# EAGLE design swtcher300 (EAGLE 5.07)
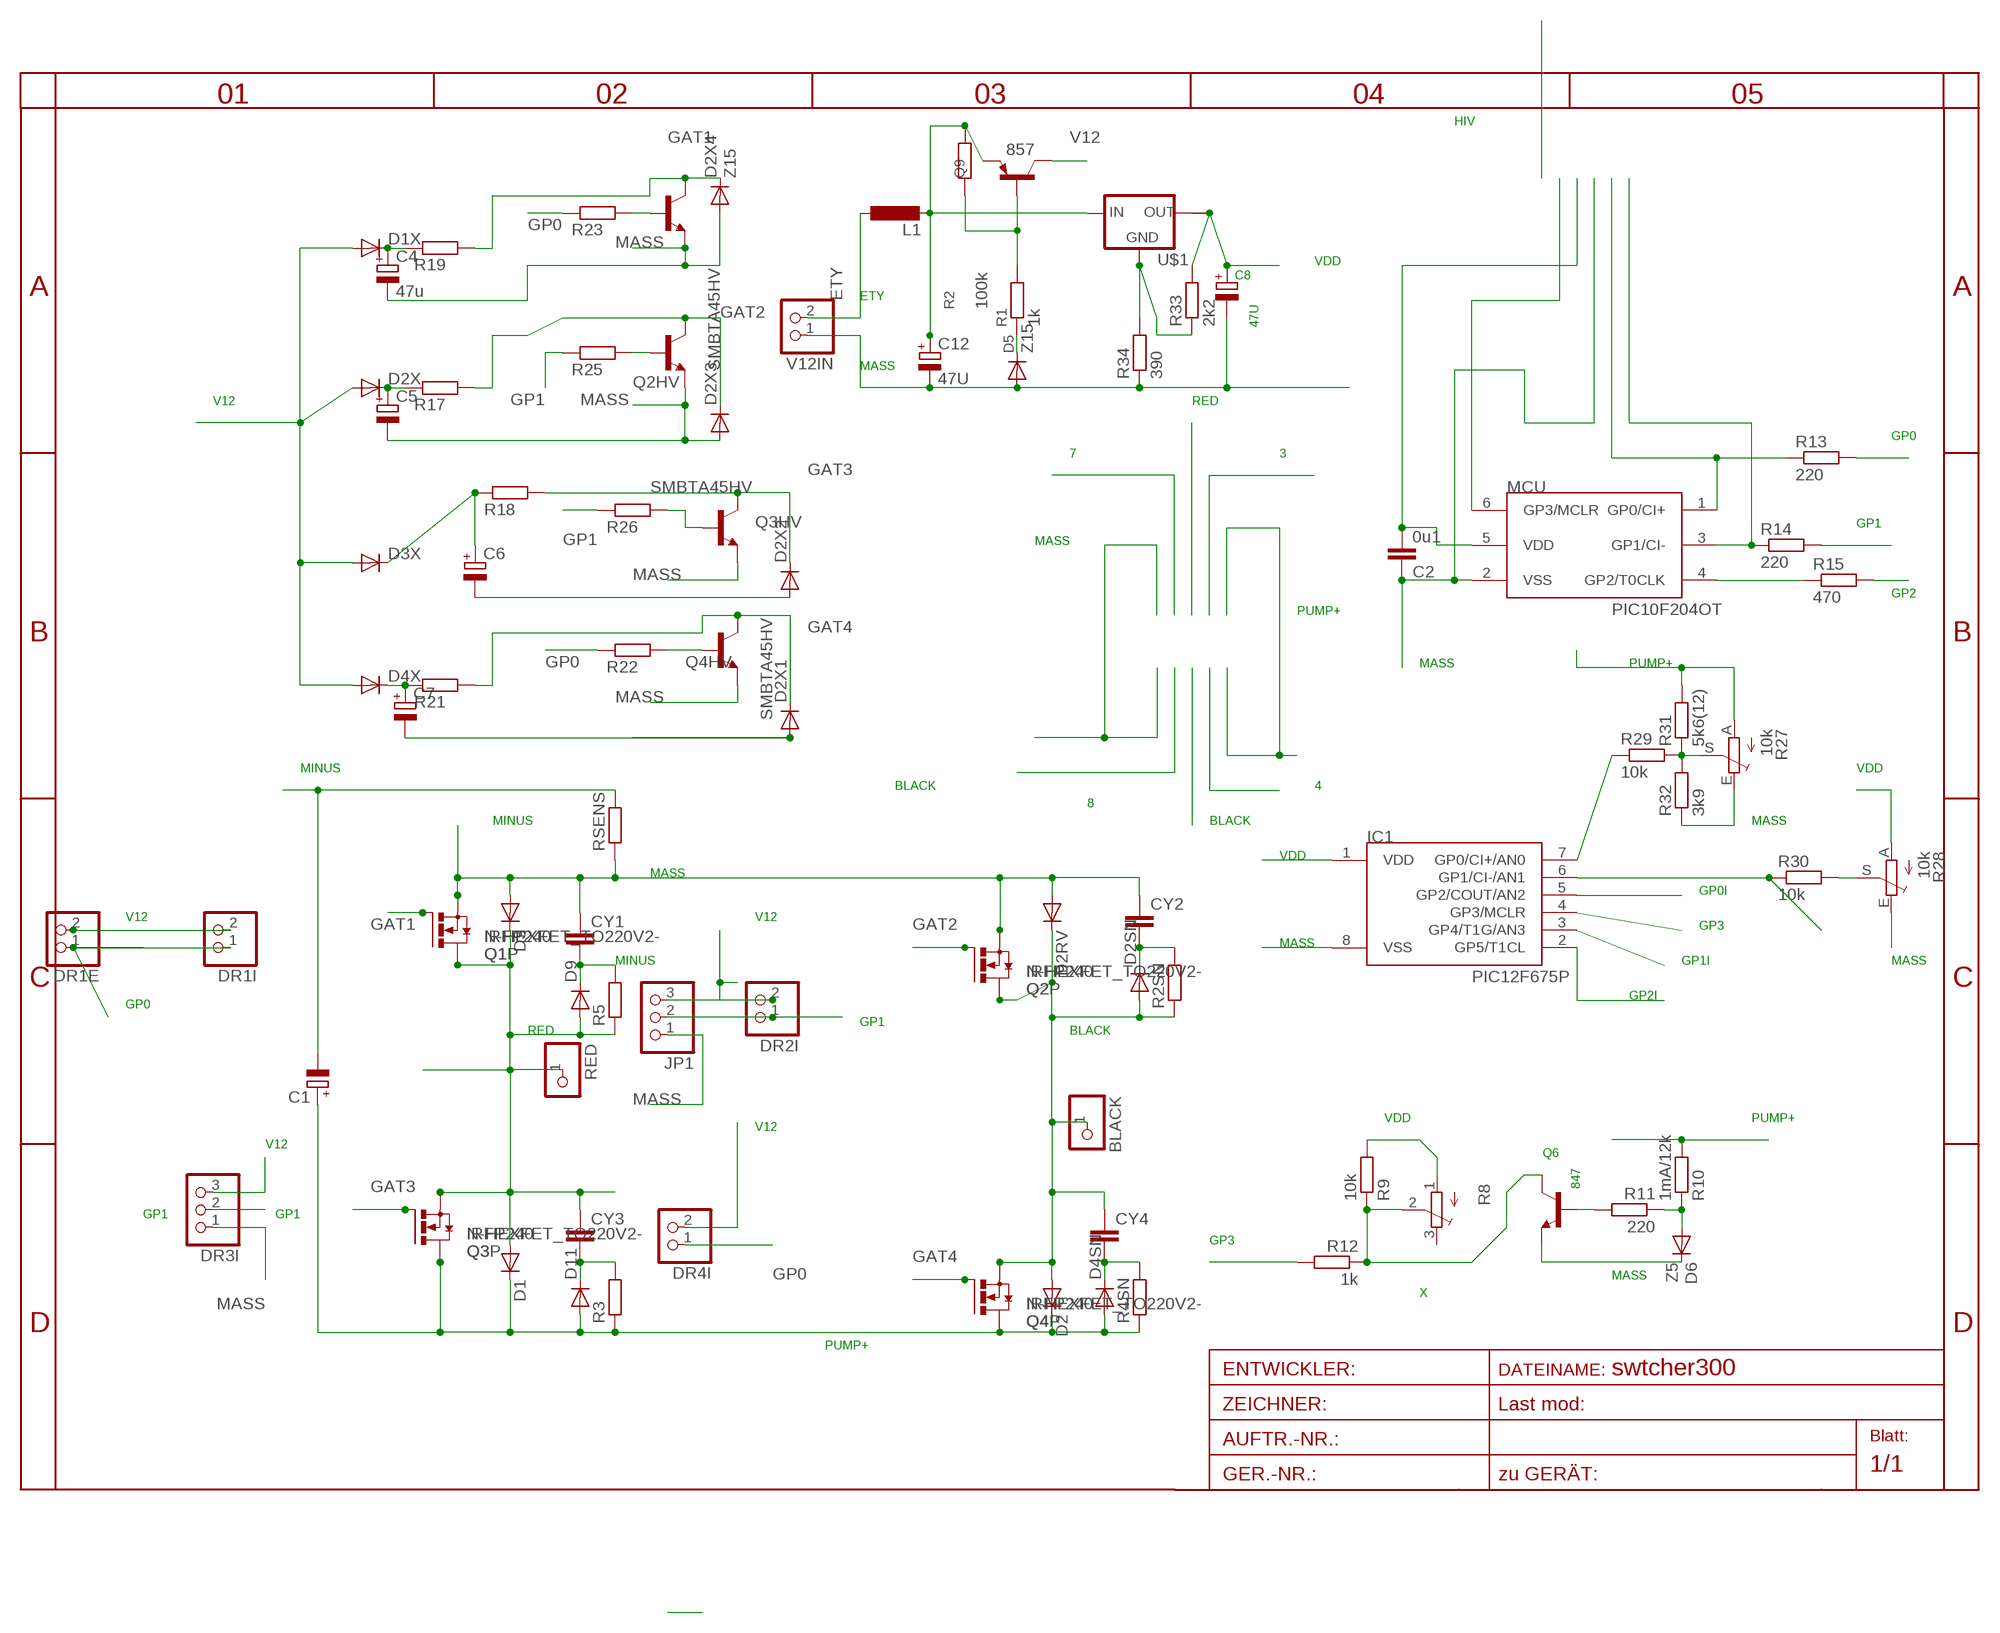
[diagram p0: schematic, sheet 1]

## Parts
BLACK  PINHD-1X14.5MM  [1X4MM5]
C1  CPOL-EUE5-13  [E5-13]
C2  0u1  C-EUC0805  [C0805]
C4  47u  CPOL-EUE  [PANASONIC_E]
C5  CPOL-EUE  [PANASONIC_E]
C6  CPOL-EUE  [PANASONIC_E]
C7  CPOL-EUE  [PANASONIC_E]
C8  47U  CPOL-EUE  [PANASONIC_E]
C12  47U  CPOL-EUE  [PANASONIC_E]
CY1  CXXC22B10  [XC22B10]
CY2  CXXC22B10  [XC22B10]
CY3  CXXC22B10  [XC22B10]
CY4  CXXC22B10  [XC22B10]
D1  DIODE-SMC  [SMC]
D1X  DIODE-SMA-DO214  [SMA-DO214AC]
D2  DIODE-SMC  [SMC]
D2RV  DIODE-SMC  [SMC]
D2SN  DIODE-SOD61E  [SOD61E]
D2X  DIODE-SMA-DO214  [SMA-DO214AC]
D2X1  DIODE-MINIMELF  [MINIMELF]
D2X2  DIODE-MINIMELF  [MINIMELF]
D2X3  DIODE-MINIMELF  [MINIMELF]
D2X4  Z15  DIODE-MINIMELF  [MINIMELF]
D3  DIODE-SMC  [SMC]
D3X  DIODE-SMA-DO214  [SMA-DO214AC]
D4SN  DIODE-SOD61E  [SOD61E]
D4X  DIODE-SMA-DO214  [SMA-DO214AC]
D5  Z15  DIODE-MINIMELF  [MINIMELF]
D6  Z5  DIODE-MINIMELF  [MINIMELF]
D9  DIODE-SOD61E  [SOD61E]
D11  DIODE-SOD61E  [SOD61E]
DR1E  PINHD-1X2STR  [1X02]
DR1I  PINHD-1X2STR  [1X02]
DR2I  PINHD-1X2STR  [1X02]
DR3I  PINHD-1X3  [1X03]
DR4I  PINHD-1X2STR  [1X02]
IC1  PIC12F675P  [DIL8]
JP1  PINHD-1X3  [1X03]
L1  L-EU0204/5  [0204/5]
MCU  PIC10F204OT  [SOT23-6]
Q1  IRFP240  [TO247BV]
Q1P  N-HEXFET_TO220V2-  [TO220BV2]
Q2  IRFP240  [TO247BV]
Q2HV  SMBTA45HV  [SOT23HV]
Q2P  N-HEXFET_TO220V2-  [TO220BV2]
Q3  IRFP240  [TO247BV]
Q3HV  SMBTA45HV  [SOT23HV]
Q3P  N-HEXFET_TO220V2-  [TO220BV2]
Q4  IRFP240  [TO247BV]
Q4HV  SMBTA45HV  [SOT23HV]
Q4P  N-HEXFET_TO220V2-  [TO220BV2]
Q6  847  BC847ALT1SMD  [SOT23]
Q9  857  BC857ALT1SMD  [SOT23-BEC]
QH1  SMBTA45HV  [SOT23HV]
R1  1k  R-EU_R0805  [R0805]
R2  100k  R-EU_R0805  [R0805]
R2SN  R-EU_0617/22  [0617/22]
R3  R-EU_0617/17  [0617/17]
R4SN  R-EU_0617/22  [0617/22]
R5  R-EU_0617/22  [0617/22]
R8  TRIM_EU-3223W  [3223W]
R9  10k  R-EU_R1206  [R1206]
R10  1mA/12k  R-EU_R1206  [R1206]
R11  220  R-EU_R1206  [R1206]
R12  1k  R-EU_0204/7  [0204/7]
R13  220  R-EU_R1206  [R1206]
R14  220  R-EU_0207/10  [0207/10]
R15  470  R-EU_0207/20  [0207/20]
R17  R-EU_R1206  [R1206]
R18  R-EU_R1206  [R1206]
R19  R-EU_R1206  [R1206]
R21  R-EU_R1206  [R1206]
R22  R-EU_R1206  [R1206]
R23  R-EU_R1206  [R1206]
R25  R-EU_R1206  [R1206]
R26  R-EU_R0805  [R0805]
R27  10k  TRIM_EU-RAND160  [RANDL]
R28  10k  TRIM_EU-RAND160  [RANDL]
R29  10k  R-EU_0207/30  [0207/30]
R30  10k  R-EU_R0805  [R0805]
R31  5k6(12)  R-EU_0207/30  [0207/30]
R32  3k9  R-EU_R0805  [R0805]
R33  2k2  R-EU_R0805  [R0805]
R34  390  R-EU_R0805  [R0805]
RED  PINHD-1X14.5MM  [1X4MM5]
RSENS  R-EU_CERAM35  [CERAM35]
U$1  AP1117  [SOT223]
V12IN  PINHD-1X2STR  [1X02]

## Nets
BLACK: BLACK.1 C7.- CY4.1 D2.A D2RV.C D2SN.A D2X1.A Q2.D Q2P.D Q4.S Q4P.S R2SN.1
ETY: L1.1 V12IN.2
GAT1: D2X4.C Q1.G Q1P.G QH1.3(C) R19.2
GAT2: D2X3.C Q2.G Q2HV.3(C) Q2P.G R17.2
GAT3: D2X2.C Q3.G Q3HV.3(C) Q3P.G R18.2
GAT4: D2X1.C Q4.G Q4HV.3(C) Q4P.G R21.2
GP0: DR1E.1 DR1I.1 DR4I.1 R13.2 R22.1 R23.1
GP0I: IC1.5(GP2/COUT/AN2) MCU.1(GP0/CI+) R13.1
GP1: DR2I.1 DR3I.2 JP1.2 R14.2 R25.1 R26.1
GP1I: IC1.3(GP4/T1G/AN3) MCU.3(GP1/CI-) R14.1
GP2: R15.2
GP2I: IC1.2(GP5/T1CL) MCU.4(GP2/T0CLK) R15.1
GP3: IC1.4(GP3/MCLR) MCU.6(GP3/MCLR) R12.2
MASS: C2.1 C4.- C5.- C8.- C12.- CY1.1 CY2.1 D2RV.A D2X3.A D2X4.A D3.A D5.A D6.C DR3I.1 IC1.8(VSS) JP1.1 MCU.2(VSS) Q1.S Q1P.S Q2.S Q2HV.2(E) Q2P.S Q3HV.2(E) Q4HV.2(E) Q6.2(E) QH1.2(E) R27.E R28.E R32.1 R34.1 RSENS.1 V12IN.1
MINUS: C1.- RSENS.2
N$1: C12.+ L1.2 Q9.E R2.2 U$1.3(IN)
N$2: Q9.B R1.2 R2.1
N$3: D5.C R1.1
N$4: D6.A R10.1 R11.1
N$5: Q6.1(B) R11.2
N$13: C6.+ D3X.K(C) R18.1
N$15: C7.+ D4X.K(C) R21.1
N$16: C5.+ D2X.K(C) R17.1
N$17: C4.+ D1X.K(C) R19.1
N$19: Q4HV.1(B) R22.2
N$21: QH1.1(B) R23.2
N$22: Q3HV.1(B) R26.2
N$23: Q2HV.1(B) R25.2
N$24: R28.S R30.2
N$30: R33.1 R34.2 U$1.1(GND)
N$31: IC1.6(GP1/CI-/AN1) R30.1
N$34: R27.S R29.2 R31.1 R32.2
N$35: IC1.7(GP0/CI+/AN0) R29.1
PUMP+: C1.+ D1.C D2.C D4SN.A D11.A Q3.D Q3P.D Q4.D Q4P.D R3.1 R4SN.1 R10.2 R27.A R31.2
RED: C6.- CY3.1 D1.A D2X2.A D3.C D9.A Q1.D Q1P.D Q3.S Q3P.S R5.1 RED.1
SNUB1: CY3.2 D11.C R3.2
SNUB2: CY4.2 D4SN.C R4SN.2
SNUB3: CY2.2 D2SN.C R2SN.2
SNUB4: CY1.2 D9.C R5.2
V12: D1X.A D2X.A D3X.A D4X.A DR1E.2 DR1I.2 DR2I.2 DR3I.3 DR4I.2 JP1.3 Q9.C
VDD: C2.2 C8.+ IC1.1(VDD) MCU.5(VDD) R8.1(A) R9.2 R28.A R33.2 U$1.2(OUT) U$1.4(TAB)
X: Q6.3(C) R8.2(S) R9.1 R12.1
Unconnected: R8.3(E)

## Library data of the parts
BLACK RED = pinhead:PINHD-1X1: PIN HEADER
C1 C4-C7 = rcl:CPOL-EU: POLARIZED CAPACITOR, European symbol
C2 = rcl:C-EU: CAPACITOR, European symbol
C8 C12 = rcl-2:CPOL-EU: POLARIZED CAPACITOR, European symbol
CY1-CY4 = rcl:CX: X CAPACITOR
D1 D1X D2 D2RV D2SN D2X D2X1-D2X4 D3 D3X D4SN D4X D5 D6 D9 D11 = diode:DIODE-: DIODE
DR1E DR1I DR2I DR4I V12IN = pinhead:PINHD-1X2: PIN HEADER
DR3I JP1 = pinhead:PINHD-1X3: PIN HEADER
IC1 = microchip-5:PIC12F6*: uPC nW 1k Program Flash memory 2x Timer Comparator 10b A/D converter/ 4xIN
L1 = rcl:L-EU: INDUCTOR, European symbol
MCU = microchip-3:PIC10F2*: uPC nW 0,25/0,5k Program Flash memory Comparator
Q1-Q4 = transistor-power:IRFP240: HEXFET Power MosFet Source: http://www.irf.com/
Q1P Q2P Q3P Q4P = transistor-power:N-HEXFET_?-*: HEXFET® Power MOSFET
Q2HV Q3HV Q4HV QH1 = transistor-npn:SMBTA45
Q6 = transistor-npn:BC847*: NPN Transistor
Q9 = transistor-pnp:BC857*: PNP Transistror
R1-R3 R13-R15 R29-R34 = rcl-2:R-EU_: RESISTOR, European symbol
R2SN R4SN R5 R9-R12 R17-R19 R21-R23 R25 R26 RSENS = rcl:R-EU_: RESISTOR, European symbol
R8 R27 R28 = pot:TRIM_EU-: POTENTIOMETER
U$1 = v-reg:AP1117

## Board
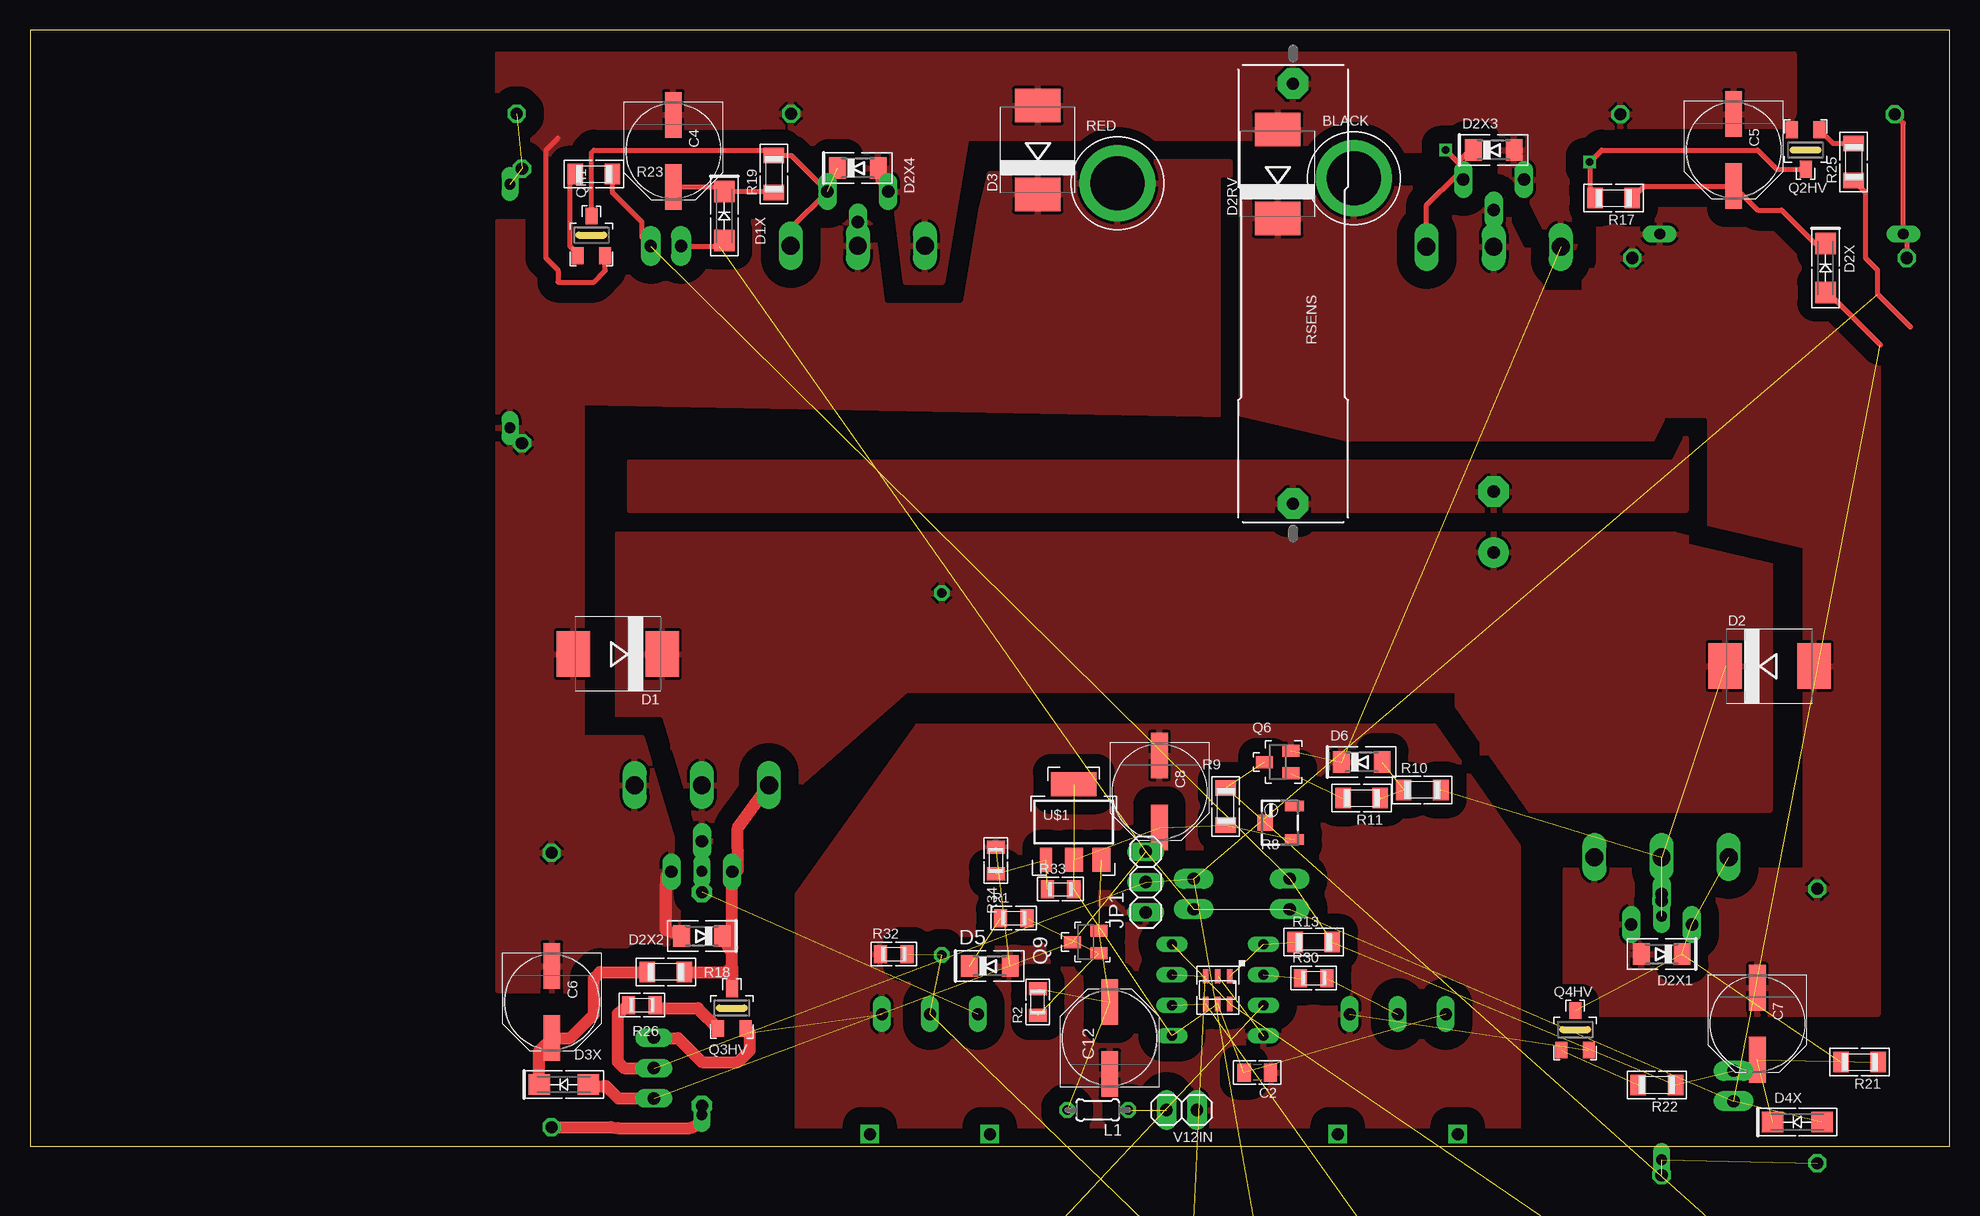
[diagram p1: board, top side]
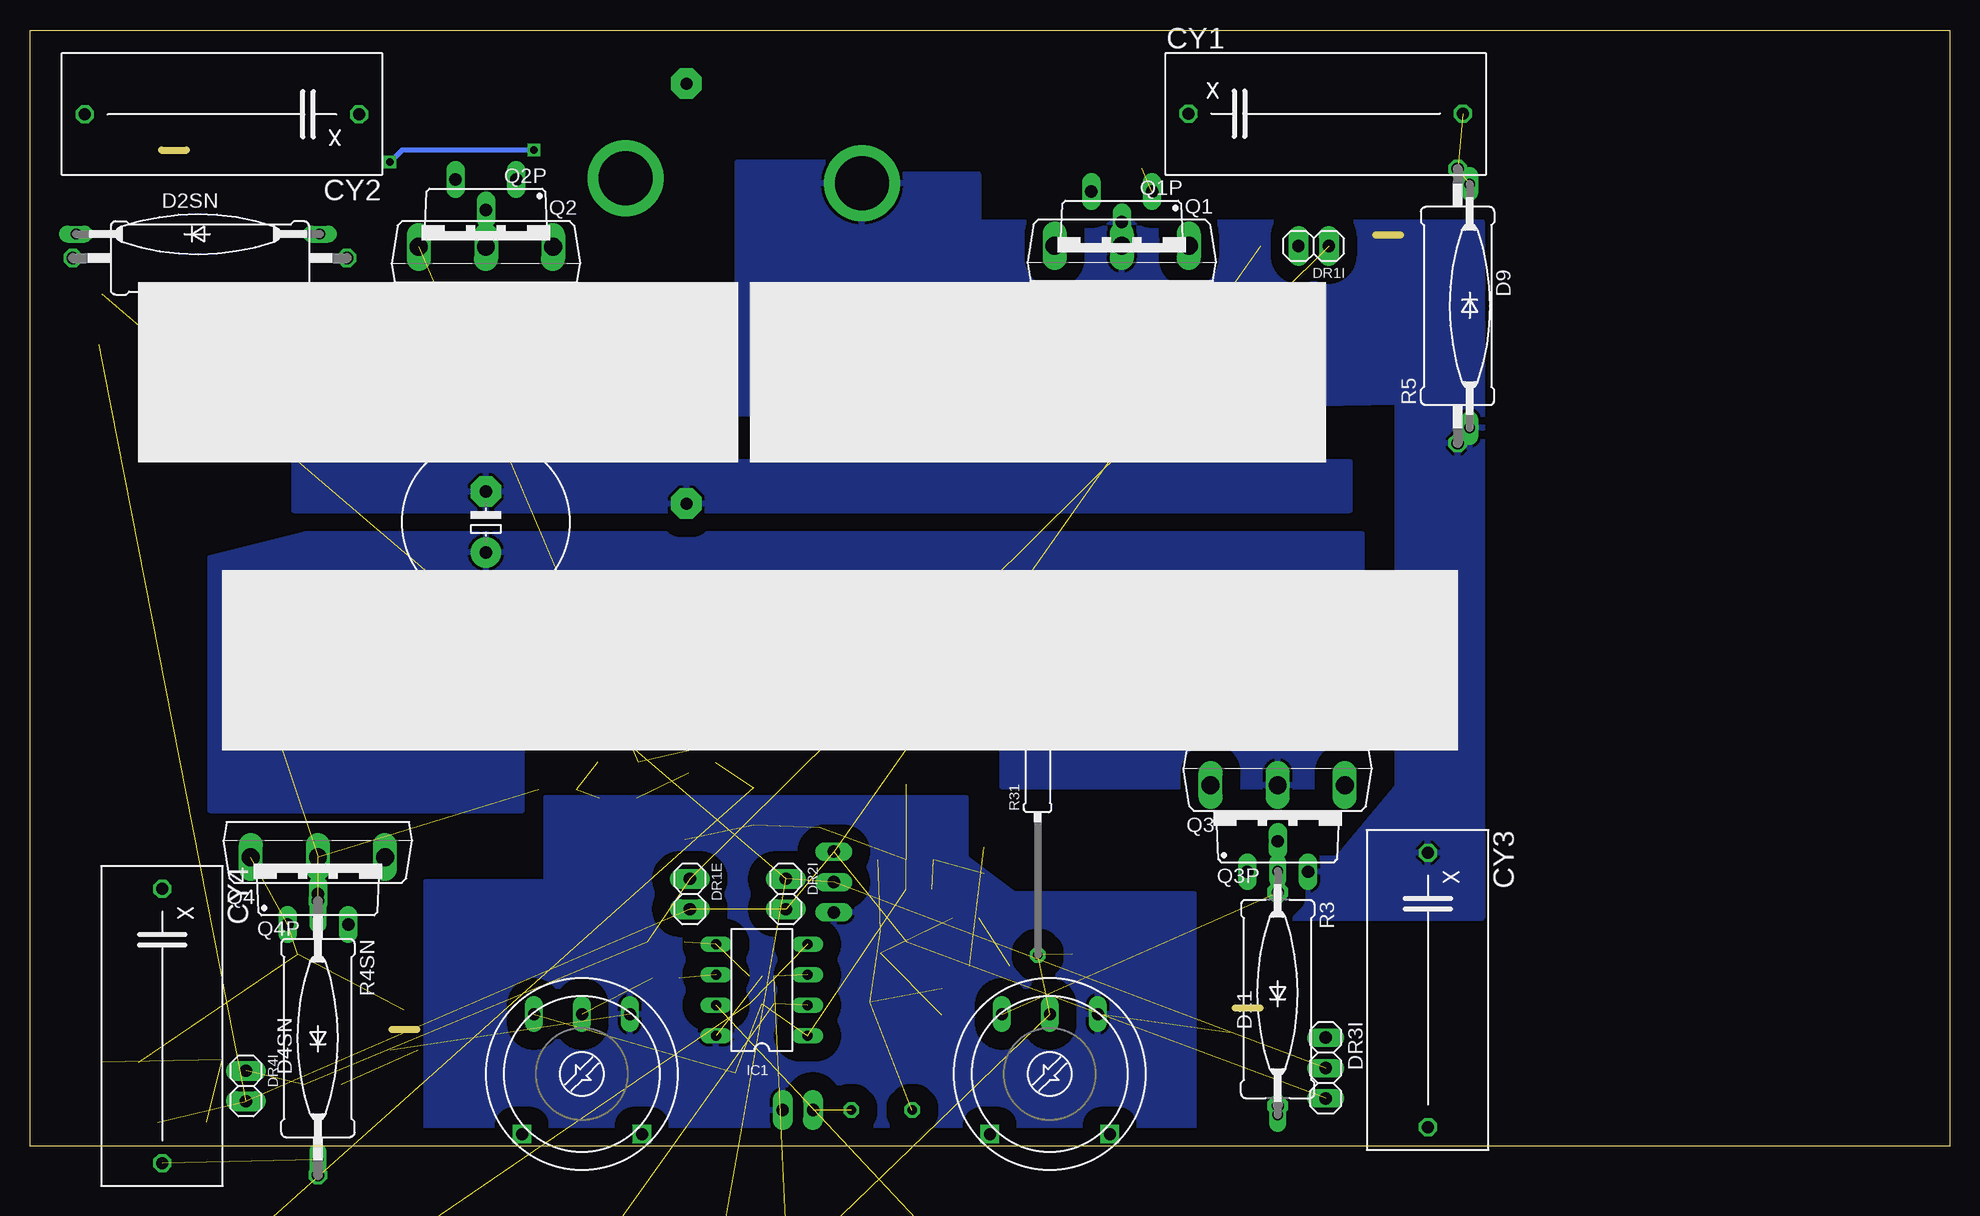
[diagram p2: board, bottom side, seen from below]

Size 160 x 93 mm. Coordinates in mm from the lower left corner, seen from the top.
Outline: 0,0 160,0 160,93 0,93 0,0
Copper layers (1*16): Top 0.035mm / dielectric 1.5mm / Bottom 0.035mm
Design rules "default *": minimum track width 10mil, minimum drill 20mil, track to track 8mil, track to pad 8mil, pad to pad 8mil, via to via 8mil, smd to smd 8mil, copper to edge 40mil, drill to drill 8mil, minimum pad ring 10mil, minimum via ring 8mil, stop-mask expansion 4mil, vias tented up to drill 0mil, thermal gap 10mil

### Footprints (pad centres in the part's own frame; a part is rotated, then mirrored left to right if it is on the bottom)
1X4MM5 = drill 4.5 pad 6.35 round: 1 0,0
E5-13 = drill 1.016 pad 2.54 round: + -2.54,0 | drill 1.016 pad 2.54 octagon: - 2.54,0
C0805 = smd 1.1 x 1.5: 1 -1.1,0; 2 1.1,0
PANASONIC_E = smd 3.8 x 1.4: + 3,0; - -3,0
XC22B10 = drill 1.016 octagon: 1 -11.43,0.025; 2 11.43,0.025
SMC = smd 2.8 x 3.8: A 3.7,0; C -3.7,0
SMA-DO214AC = smd 1.8 x 1.7: A 2.05,-0.127; K -2.05,-0.127
SOD61E = drill 0.914 long: A 10.16,0; C -10.16,0
MINIMELF = smd 1.4 x 1.8: A 1.7,0; C -1.7,0
1X02 = drill 1.016 pad 1.676 long: 1 -1.27,0; 2 1.27,0
1X03 = drill 1.016 long: 1 -2.54,0; 2 0,0; 3 2.54,0
DIL8 = drill 0.8 long: 1 -3.81,-3.81; 2 -1.27,-3.81; 3 1.27,-3.81; 4 3.81,-3.81; 5 3.81,3.81; 6 1.27,3.81; 7 -1.27,3.81; 8 -3.81,3.81
0204/5 = drill 0.813 octagon: 1 -2.54,0; 2 2.54,0
SOT23-6 = smd 0.45 x 1.2: 1 -1.016,-1.15; 2 0,-1.15; 3 1.016,-1.15; 4 1.016,1.15; 5 0,1.15; 6 -1.016,1.15
TO247BV = drill 1.499 long: D 0,-2.921; G -5.588,-2.921; S 5.588,-2.921
TO220BV2 = drill 1.016 long: D 0,0; G -2.54,-2.54; S 2.54,-2.54
SOT23HV = smd 1 x 1.4: 1 -1.15,-1.7; 2 1.15,-1.7; 3 0,1.6
SOT23 = smd 1 x 1.4: 1 -0.95,-1.1; 2 0.95,-1.1; 3 0,1.1
SOT23-BEC = smd 1 x 1.4: B -0.95,-1.1; C 0,1.1; E 0.95,-1.1
R0805 = smd 1.1 x 1.5: 1 -1.1,0; 2 1.1,0
0617/22 = drill 1.016 octagon: 1 -11.43,0; 2 11.43,0
0617/17 = drill 1 pad 1.676 octagon: 1 -8.89,0; 2 8.89,0
3223W = smd 0.9 x 1.6: 1 -1.4,-1.215; 3 1.4,-1.215 | smd 1.3 x 1.3: 2 0,1.215
R1206 = smd 1.3 x 1.7: 1 -1.55,0; 2 1.55,0
0204/7 = drill 0.813 octagon: 1 -3.81,0; 2 3.81,0
0207/10 = drill 0.813 octagon: 1 -5.08,0; 2 5.08,0
0207/20 = drill 0.813 octagon: 1 -10.08,0; 2 10.08,0
RANDL = drill 1 long: A -4,5; E 4,5; S 0,5 | drill 1 square: P$1 -5,-5; P$2 5,-5
0207/30 = drill 0.813 octagon: 1 -15.08,0; 2 15.08,0
CERAM35 = drill 1 pad 2.54 octagon: 1 -17.5,0; 2 17.5,0
SOT223 = smd 1 x 2: 1 -2.3,-3.15 | smd 1.5 x 2: 2 0,-3.15; 3 2.3,-3.15 | smd 3.8 x 2: 4 0,3.15

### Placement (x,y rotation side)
BLACK  110.35,80.64 0 top
C1  122,52 90 bottom
C2  102.3,6.12 180 top
C4  53.62,82.92 270 top
C5  142,83 270 top
C6  43.5,12 270 top
C7  143.98,10.19 270 top
C8  94.15,29.54 270 top
C12  90,9 90 top
CY1  52,86 0 bottom
CY2  144,86 180 bottom
CY3  43.5,13 270 bottom
CY4  149,10 270 bottom
D1  49,41 180 top
D1X  58,77.5 270 top
D2  145,40 0 top
D2RV  104,81 90 top
D2SN  146,76 0 bottom
D2X  149.78,73.17 270 top
D2X1  136,16 180 top
D2X2  56,17.5 180 top
D2X3  122,83 0 top
D2X4  69,81.5 0 top
D3  84,83 90 top
D3X  44.5,5.25 0 top
D4SN  136,9 90 bottom
D4X  147.31,2.12 0 top
D5  80,15 0 top
D6  111,32 0 top
D9  40,70 270 bottom
D11  56,12.75 90 bottom
DR1E  105,21 270 bottom
DR1I  53,75 180 bottom
DR2I  97,21 270 bottom
DR3I  52,6.5 270 bottom
DR4I  142,5 270 bottom
IC1  99,13 90 bottom
JP1  93,22 90 top
L1  89,3 180 top
MCU  99,13 180 top
Q1  69,72.1 180 bottom
Q1P  69,77 180 bottom
Q2  122,72 180 bottom
Q2HV  148,83 180 top
Q2P  122,78 180 bottom
Q3  56,33 0 bottom
Q3HV  58.5,11.5 0 top
Q3P  56,25.4 0 bottom
Q4  136,27 0 bottom
Q4HV  128.8,9.7 0 top
Q4P  136,21 0 bottom
Q6  104,32 90 top
Q9  88,17 90 top
QH1  46.8,75.9 0 top
R1  82,19 0 top
R2  84,12 90 top
R2SN  145,74 180 bottom
R3  56,12.25 270 bottom
R4SN  136,9 270 bottom
R5  41,70 90 bottom
R8  104.18,26.94 90 top
R9  99.67,28.3 270 top
R10  116.05,29.67 0 top
R11  111,29 180 top
R12  not placed on the board
R13  107,17 0 top
R14  not placed on the board
R15  not placed on the board
R17  132,79 180 top
R18  53,14.5 0 top
R19  62,81 90 top
R21  152.5,7 180 top
R22  135.6,5.1 180 top
R23  47,81 180 top
R25  152,82 90 top
R26  51,11.75 0 top
R27  75,6 0 bottom
R28  114,6 0 bottom
R29  not placed on the board
R30  107,14 0 top
R31  76,31 90 bottom
R32  72,16 0 top
R33  85.9,21.4 0 top
R34  80.5,23.8 270 top
RED  90.65,80.23 0 top
RSENS  105.29,71.04 270 top
U$1  87,27 0 top
V12IN  96,3 180 top

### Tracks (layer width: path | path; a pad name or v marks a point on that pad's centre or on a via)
BLACK
  pour Top (isolate 1.5, rank 2): 101,79 117,80 117,83 154,83 154,11 128,11 128,23 148,23 148,50 101,61
ETY  (1 unrouted)
GAT1  (1 unrouted)
  Top 0.406: Q1.G 63.41,76.49 Q1P.G 63.45,82.55 R19.2 61.55,83 47,83 46.8,82.8 QH1.3
GAT2  (via drill 0.6)
  Top 0.406: 119,82 119.46,81.54 Q2P.G 119,81 116.41,78.41 Q2.G | 119,82 v118,83 | R17.2 130,79.45 v130,82 131,83 144,83 145.6,81.4 Q2HV.3 | D2X3.C 120,83 119,82
  Bottom 0.406: v118,83 129,83 v130,82
GAT3
  Top 1: 58.5,15 58.5,16.2 58.35,16.35 | 58.5,15 Q3HV.3 | 58.35,16.35 D2X2.C | Q3.G 58.99,26.49 59,23 58.68,23 Q3P.G 58.54,16.54 58.35,16.35 | R18.2 58,14.5 58.5,15
GAT4  (4 unrouted)
GP0  (4 unrouted)
  Top 0.406: R23.1 48.55,79.45 51,77 51,75.73 DR1I.1
GP0I  (2 unrouted)
GP1  (4 unrouted)
  Top 0.406: 156.77,68.23 154,71 154,73 153,74 153,79.45 R25.1
  Top 1: DR3I.2 49.5,6.5 49,7 49,11.05 R26.1
GP1I  (2 unrouted)
GP2I  (2 unrouted)
GP3  (2 unrouted)
MASS  (6 unrouted)
  Top 0.406: D2X4.A 70.7,80.38 Q1P.S | QH1.2 47.95,72.95 47,72 44,72 44,73 43,74 43,83 44,84
  Top 1: DR3I.1 52,9 54,9 56,7 59,7 60,8 60,9.45 Q3HV.2
  pour Top (isolate 1.5): 39,91 147,91 147,85 132,85 128,73 125,79 119,83 105,83 104,84 78,84 76,72 73,72 72,80 70,81 39,81
  pour Top (isolate 1.5, rank 3): 74,35 117,35 124,25 124,1 64,1 64,21
  pour Bottom (isolate 1.5, rank 3): 82,29 117,29 117,22 127,22 127,1 63,1 63,21 78,21 82,24
MINUS
  pour Top (isolate 1.5): 138,53 50,53 50,57 137,57 138,59
  pour Bottom (isolate 1.5): 138,53 50,53 50,57 137,57 138,59
N$1  (4 unrouted)
N$2  (2 unrouted)
N$3  (1 unrouted)
N$4  (2 unrouted)
N$5  (1 unrouted)
N$13
  Top 1: D3X.K 42.45,7.95 C6.+ 45,9 47,11 47,14 47.5,14.5 R18.1
N$15  (2 unrouted)
N$16
  Top 0.406: D2X.K 148.78,75.22 146,78 144,78 C5.+ 134.55,80 R17.1
N$17
  Top 0.406: C4.+ 57.5,79.92 D1X.K 61.9,79.55 R19.1
N$19  (1 unrouted)
N$21
  Top 0.406: QH1.1 45.65,74.35 45,75 45,80.55 R23.2
N$22
  Top 1: Q3HV.1 55.65,11.5 52.35,11.5 R26.2
N$23
  Top 0.406: R25.2 150.3,83.55 Q2HV.1
N$24  (1 unrouted)
N$30  (2 unrouted)
N$31  (1 unrouted)
N$34  (3 unrouted)
N$35  (1 unrouted)
PUMP+  (6 unrouted)
  Top 0.5: R3.1 D11.A
  Top 1: D11.A Q3P.D
  pour Top (isolate 1.5, rank 4): 145,49 145,28 119,28 119,38 73,38 57,24 49,24 49,51 137,51
  pour Bottom (isolate 1.5): 145,49 145,28 119,28 119,38 79,38 79,30 49,30 49,51 137,51
RED
  Top 1: D2X2.A 53,18 53,22.4 Q3P.S
  pour Top (isolate 1.5, rank 3): 100,61 100,82 90,83 90,81 80,81 79,77 39,77 39,13 54,13 54,24 51,34 46,34 46,62
  pour Bottom (isolate 1.5, rank 2): 101,61 101,82 90,82 90,81 81,81 81,77 39,77 39,19 61,19 61,24 51,24 46,30 46,62
SNUB1
  Top 0.5: 56,2 D11.C R3.2
  Top 1: CY3.2 48.43,1.57 49,1.5 55,1.5 56,2
SNUB2  (2 unrouted)
SNUB3
  Top 0.406: R2SN.2 156.43,75.73 D2SN.C 156.16,85.25 CY2.2
SNUB4  (2 unrouted)
V12  (8 unrouted)
  Top 0.406: DR1I.2 57.42,75 D1X.A | 154.23,66.77 150,71 149.77,71 D2X.A
  Top 1: DR3I.3 49.04,3.96 48,5 46.67,5 D3X.A
VDD  (9 unrouted)
X  (3 unrouted)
